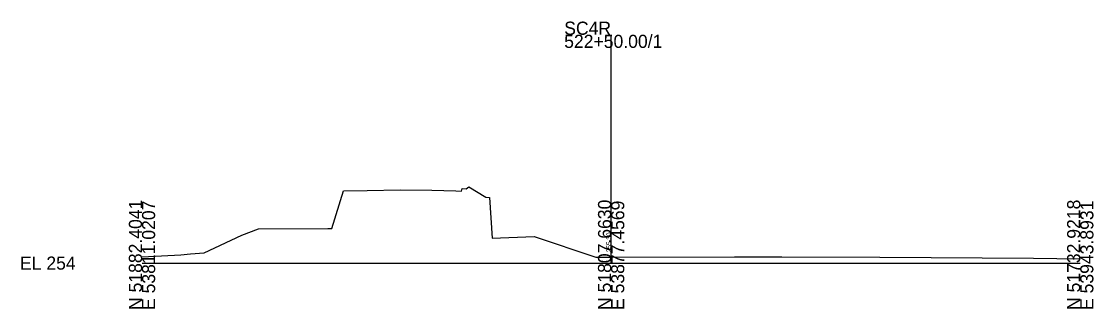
# Model space of a CAD drawing. Extents: x 8330 to 11559, y 6854 to 26418.
# Drawn here: x 9330.1 to 9558.7, y 21354.5 to 21415.7 of the extents above; entities that cross this region are included whole.
import ezdxf

# ---------------------------------------------------------------- set-up
doc = ezdxf.new("R2010")
doc.units = 0
for name, color, linetype in [('Level 10', 7, 'Continuous'), ('Level 60', 7, 'Continuous'), ('Level 63', 7, 'Continuous')]:
    doc.layers.add(name, color=color, linetype=linetype)

msp = doc.modelspace()

# ---------------------------------------------------------------- linework, layer by layer
at = {"layer": 'Level 60'}
for p, q in [((9396.33, 21371.57), (9398.77, 21379.54)), ((9398.77, 21379.54), (9403.84, 21379.67)), ((9403.84, 21379.67), (9410.84, 21379.8)), ((9410.84, 21379.8), (9417.6, 21379.69)), ((9417.6, 21379.69), (9422.72, 21379.57)), ((9422.72, 21379.57), (9423.92, 21379.52)), ((9423.92, 21379.52), (9424.09, 21380.04)), ((9424.09, 21380.04), (9424.91, 21380)), ((9424.91, 21380), (9425.48, 21380.4)), ((9425.48, 21380.4), (9429.09, 21378.2)), ((9429.09, 21378.2), (9429.91, 21378.18)), ((9429.91, 21378.18), (9430.48, 21369.52)), ((9377.11, 21370.15), (9380.68, 21371.48)), ((9380.68, 21371.48), (9395.43, 21371.54)), ((9395.43, 21371.54), (9396.33, 21371.57)), ((9369.1, 21366.39), (9377.11, 21370.15)), ((9430.48, 21369.52), (9439.44, 21369.82)), ((9439.44, 21369.82), (9452.6, 21365.47)), ((9355.83, 21365.54), (9364.14, 21365.91)), ((9364.14, 21365.91), (9366.15, 21366.15)), ((9366.15, 21366.15), (9369.1, 21366.39)), ((9452.6, 21365.47), (9455.83, 21365.47)), ((9455.83, 21365.47), (9482.11, 21365.52)), ((9482.11, 21365.52), (9492.25, 21365.48)), ((9492.25, 21365.48), (9513.1, 21365.42)), ((9513.1, 21365.42), (9545.87, 21365.2)), ((9545.87, 21365.2), (9555.83, 21365.07))]:
    msp.add_line(p, q, dxfattribs=at)
at = {"layer": 'Level 63'}
for p, q in [((9455.83, 21364.17), (9455.83, 21412.84)), ((9355.83, 21364.17), (9455.83, 21364.17)), ((9455.83, 21364.17), (9555.83, 21364.17))]:
    msp.add_line(p, q, dxfattribs=at)

# ---------------------------------------------------------------- texts
at = {"layer": 'Level 10'}
msp.add_text('255.30', height=1, rotation=90, dxfattribs=at).set_placement((9455.83, 21366.47))
at = {"layer": 'Level 63'}
for s, p in [('SC4R', (9445.83, 21412.84)), ('522+50.00/1', (9445.82, 21410.04)), ('EL 254', (9329.82, 21362.77))]:
    msp.add_text(s, height=2.8, dxfattribs=at).set_placement(p)
for s, p in [('N 51882.4041', (9355.83, 21354.17)), ('E 53811.0207', (9358.63, 21354.17)), ('N 51807.6630', (9455.83, 21354.17)), ('E 53877.4569', (9458.63, 21354.17)), ('N 51732.9218', (9555.83, 21354.17)), ('E 53943.8931', (9558.63, 21354.17))]:
    msp.add_text(s, height=2.8, rotation=90, dxfattribs=at).set_placement(p)

doc.saveas('drawing.dxf')
